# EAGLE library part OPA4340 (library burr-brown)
Operational Amplifiers Source: http://focus.ti.com/lit/ds/sbos073/sbos073.pdf
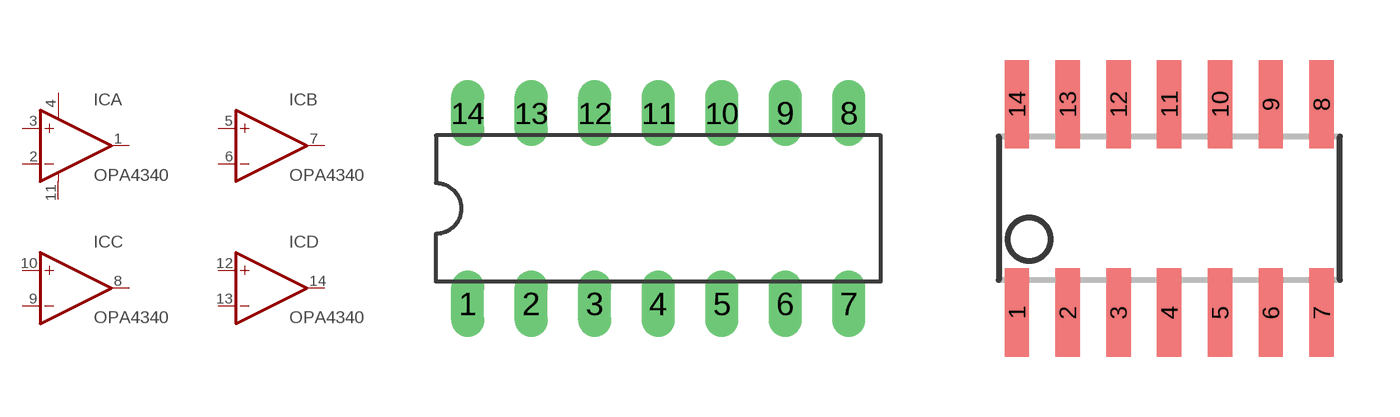
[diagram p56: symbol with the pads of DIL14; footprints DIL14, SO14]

Designator prefix IC; gates A=OP-AMP+- B=OP-AMP C=OP-AMP D=OP-AMP

## OPA4340P (OC_FARNELL: unknown; OC_NEWARK: unknown)  [DIL14]
1  A:OUT  out
2  A:-IN  in
3  A:+IN  in
4  A:V+  pwr
5  B:+IN  in
6  B:-IN  in
7  B:OUT  out
8  C:OUT  out
9  C:-IN  in
10  C:+IN  in
11  A:V-  pwr
12  D:+IN  in
13  D:-IN  in
14  D:OUT  out

## OPA4340U (MF: TEXAS INSTRUMENTS; MPN: OPA4340UA; OC_FARNELL: 1212307; OC_NEWARK: 35C1907)  [SO14]
Pads as for DIL14

## OPA4340E (MPN: OPA4340EA/250G4; OC_FARNELL: 1207061; OC_NEWARK: 67K8209)  [SSOP16BU]
1  A:OUT  out
2  A:-IN  in
3  A:+IN  in
4  A:V+  pwr
5  B:+IN  in
6  B:-IN  in
7  B:OUT  out
10  C:OUT  out
11  C:-IN  in
12  C:+IN  in
13  A:V-  pwr
14  D:+IN  in
15  D:-IN  in
16  D:OUT  out

## Footprint DIL14 (pad centres in mm)
Dual In Line Package
drill 0.813 long: 1 -7.62,-3.81; 2 -5.08,-3.81; 3 -2.54,-3.81; 4 0,-3.81; 5 2.54,-3.81; 6 5.08,-3.81; 7 7.62,-3.81; 8 7.62,3.81; 9 5.08,3.81; 10 2.54,3.81; 11 0,3.81; 12 -2.54,3.81; 13 -5.08,3.81; 14 -7.62,3.81

## Footprint SO14 (pad centres in mm)
Small Outline Package
smd 0.61 x 2.21: 1 -3.81,-2.603; 2 -2.54,-2.603; 3 -1.27,-2.603; 4 0,-2.603; 5 1.27,-2.603; 6 2.54,-2.603; 7 3.81,-2.603; 8 3.81,2.603; 9 2.54,2.603; 10 1.27,2.603; 11 0,2.603; 12 -1.27,2.603; 13 -2.54,2.603; 14 -3.81,2.603

## Footprint SSOP16BU (pad centres in mm)
Small Shrink Outline Package Source: http://focus.ti.com/lit/ml/msoi004e/msoi004e.pdf
smd 0.348 x 1.397: 1 -2.223,-2.619; 2 -1.588,-2.62; 3 -0.953,-2.62; 4 -0.318,-2.62; 5 0.318,-2.62; 6 0.953,-2.62; 7 1.588,-2.62; 8 2.223,-2.62; 9 2.223,2.62; 10 1.588,2.62; 11 0.953,2.62; 12 0.318,2.62; 13 -0.318,2.62; 14 -0.953,2.62; 15 -1.588,2.62; 16 -2.223,2.62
